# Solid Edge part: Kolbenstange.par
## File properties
Last saved by: bmolnar
Revision: 77
Dokumentum tartalom típus: 0
Sűrűség: 0,000 kg/m^3
Pontosság: 0,990
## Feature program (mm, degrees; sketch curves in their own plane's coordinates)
base feature "unnamed BaseFeature 1"
thread "unnamed Thread 1"
sketch for "Kihúzás_1" plane through (27.5, 0, 0) normal (1, 0, 0) x-axis (0, -1, 0)
  circle centre (0, 0) radius 25
extrude "Kihúzás_1" add finite 8 along +normal
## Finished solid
Body 1: solid body, 14 faces, 20 edges, 8 vertices.
  Faces by surface: plane 7, cylinder 4, cone 2, torus 1
  Edges by curve: circle 10, line 6, ellipse 2, intersection 2
Bounding box of the edges (mm; curved faces can reach further): 35.500 x 50.000 x 50.000, from (0, -25, -25) to (35.5, 25, 25).
Cylindrical faces by radius (mm): R4.188 x2, R8 x1, R25 x1
Conical faces (half-angle, radius in mm at the cone's reference point): 45 deg R4.538 x1, 59 deg R2.094 x1
Toroidal faces (ring radius, tube radius in mm): R6.3 r1.7 x1
Planar faces by outward normal: +x 1, +z 1, -x 2, -z 1, oblique 2
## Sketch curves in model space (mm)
circle centre (27.5, 0, 0) radius 25
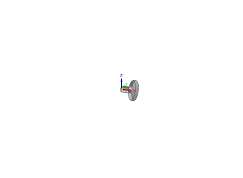
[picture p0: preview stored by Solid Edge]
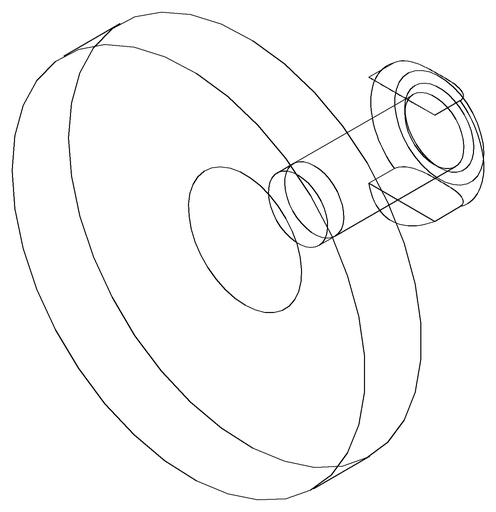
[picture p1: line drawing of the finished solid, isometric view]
